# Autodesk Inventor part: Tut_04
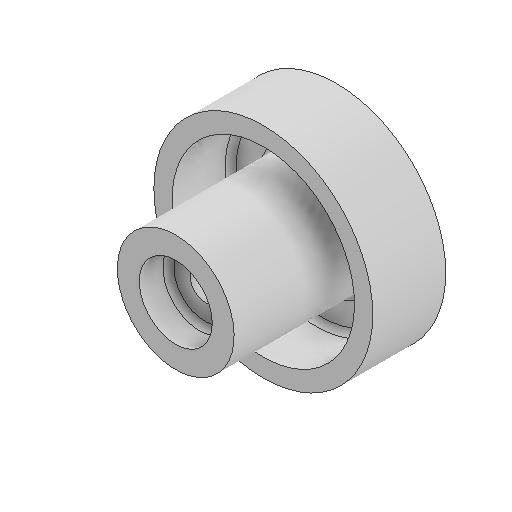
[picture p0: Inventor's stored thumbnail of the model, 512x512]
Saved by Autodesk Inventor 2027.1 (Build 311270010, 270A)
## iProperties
Created: 2019-02
Part Number: Tut_04
Material: Generic
Document SubType Name: Modeling
Designer: LENOVO-CADCIM
Density: 1 g/cm^3
Appearance: Default
Author: LENOVO-CADCIM
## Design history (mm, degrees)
revolve "Revolution1" stored, may be unused: angle "d31" = 90 deg
body "Solid1"
sketch "Sketch1"
  geometry: L1 (0, 0)-(0, 22); L2 (0, 22)-(4, 22); L3 (4, 22)-(4, 36); L4 (4, 36)-(8.5, 36); L5 (10, 37.5)-(10, 44); L6 (10, 44)-(16, 44); L7 (16, 44)-(16, 5.5); L8 (17.5, 4)-(23.5, 4); L9 (25, 5.5)-(25, 20); L10 (25, 20)-(30, 20); L11 (30, 20)-(30, 0); L12 (30, 0)-(0, 0); A1 r 1.5 centre (8.5, 37.5) between (8.5, 36) and (10, 37.5); A2 r 1.5 centre (17.5, 5.5) between (16, 5.5) and (17.5, 4); A3 r 1.5 centre (23.5, 5.5) between (23.5, 4) and (25, 5.5); 4 further points
  constraints: 24 end point, 11 perpendicular, 6 point on circle, 6 point on line, 6 tangent, 3 centre point, 1 equal radius, 1 midpoint, 1 vertical
  dimensions: "d21" = 22 distance of L1.start L1.end; "d22" = 36 distance between parallel lines of L12 L4; "d23" = 44 distance between parallel lines of L12 L6; "d24" = 25 distance between parallel lines of L9 L1; "d25" = 30 distance from line of point (30, 10) L1; "d26" = 4 distance between parallel lines of L8 L12; "d27" = 4 distance between parallel lines of L1 L3; "d28" = 10 distance between parallel lines of L5 L1; "d29" = 16 distance between parallel lines of L7 L1; "d30" = 20 distance of L10.end L11.end; "d32" = 1.5 radius of A1; "d33" = 1.5 radius of A2 (derived)
